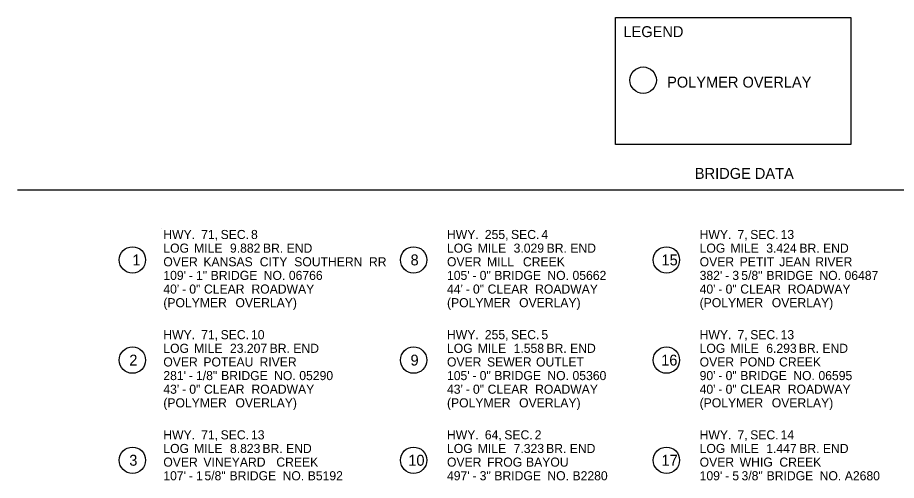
# Model space of a CAD drawing. Extents: x 1930546 to 1934225, y 596452 to 599553.
# Drawn here: x 1930546 to 1931513, y 599044 to 599553 of the extents above; entities that cross this region are included whole.
import ezdxf

# ---------------------------------------------------------------- set-up
doc = ezdxf.new("R2010")
doc.units = 0
doc.layers.add('Default', color=7, linetype='Continuous')
doc.layers.add('R_Border', color=7, linetype='Continuous')

msp = doc.modelspace()

# ---------------------------------------------------------------- linework, layer by layer
at = {"layer": 'R_Border'}
for p, q in [((1932141.6, 599363.54), (1930546.24, 599363.54)), ((1930704.61, 599321.69), (1930704.61, 599321.69))]:
    msp.add_line(p, q, dxfattribs=at)
msp.add_lwpolyline([(1931203.83, 599553.27), (1931462.74, 599553.27), (1931462.74, 599413.76), (1931203.83, 599413.76)], close=True, dxfattribs=at)
for centre in [(1931234.29, 599484.4), (1930672.53, 599286.71), (1930981.88, 599286.71), (1931259.86, 599286.71), (1930672.53, 599176.53), (1930981.88, 599176.53), (1931259.86, 599176.53), (1930672.53, 599066.36), (1930981.88, 599066.36), (1931259.86, 599066.36)]:
    msp.add_circle(centre, 14.52, dxfattribs=at)

# ---------------------------------------------------------------- texts
at = {"layer": 'Default'}
for s, p in [('HWY.', (1930706.56, 599309.69)), (' 71,', (1930744.47, 599309.69)), (' SEC.', (1930765.87, 599309.69)), (' 8', (1930799.28, 599309.69)), ('HWY.', (1931018.56, 599309.69)), (' 255,', (1931056.47, 599309.69)), (' SEC.', (1931085.26, 599309.69)), (' 4', (1931118.67, 599309.69)), ('HWY.', (1931296.43, 599309.69)), (' 7,', (1931334.34, 599309.69)), (' SEC.', (1931348.36, 599309.69)), (' 13', (1931381.77, 599309.69)), ('LOG', (1930706.56, 599294.69)), (' MILE', (1930736.69, 599294.69)), (' 9.882', (1930776.13, 599294.69)), (' BR.', (1930812.45, 599294.69)), (' END', (1930838.48, 599294.69)), ('LOG', (1931018.56, 599294.69)), (' MILE', (1931048.69, 599294.69)), (' 3.029', (1931088.13, 599294.69)), (' BR.', (1931124.43, 599294.69)), (' END', (1931150.46, 599294.69)), ('LOG', (1931296.43, 599294.69)), (' MILE', (1931326.56, 599294.69)), (' 3.424', (1931366, 599294.69)), (' BR.', (1931402.43, 599294.69)), (' END', (1931428.46, 599294.69)), ('OVER', (1930706.56, 599279.69)), (' KANSAS', (1930746.89, 599279.69)), (' CITY', (1930808.88, 599279.69)), (' SOUTHERN', (1930846.81, 599279.69)), (' RR', (1930929.03, 599279.69)), ('OVER', (1931018.56, 599279.69)), (' MILL', (1931058.89, 599279.69)), (' CREEK', (1931098.35, 599279.69)), ('OVER', (1931296.43, 599279.69)), (' PETIT', (1931336.76, 599279.69)), (' JEAN', (1931380.26, 599279.69)), (' RIVER', (1931419.83, 599279.69)), ("109'", (1930706.56, 599264.69)), (' 1"', (1930738.79, 599264.69)), (' BRIDGE', (1930754.92, 599264.69)), (' NO.', (1930813.24, 599264.69)), (' 06766', (1930840.9, 599264.69)), ("105'", (1931018.56, 599264.69)), (' 0"', (1931050.79, 599264.69)), (' BRIDGE', (1931066.92, 599264.69)), (' NO.', (1931125.24, 599264.69)), (' 05662', (1931152.9, 599264.69)), ("382'", (1931296.43, 599264.69)), (' 3', (1931328.66, 599264.69)), (' 5/8"', (1931338.51, 599264.69)), (' BRIDGE', (1931366.14, 599264.69)), (' NO.', (1931424.45, 599264.69)), (' 06487', (1931452.11, 599264.69)), (' -', (1930730.76, 599264.69)), (' -', (1931042.76, 599264.69)), (' -', (1931320.64, 599264.69)), ("40'", (1930706.56, 599249.69)), (' -', (1930723.37, 599249.69)), (' 0"', (1930731.4, 599249.69)), (' CLEAR', (1930747.53, 599249.69)), (' ROADWAY', (1930799.75, 599249.69)), ("44'", (1931018.56, 599249.69)), (' -', (1931035.37, 599249.69)), (' 0"', (1931043.4, 599249.69)), (' CLEAR', (1931059.53, 599249.69)), (' ROADWAY', (1931111.75, 599249.69)), ("40'", (1931296.43, 599249.69)), (' -', (1931313.25, 599249.69)), (' 0"', (1931321.28, 599249.69)), (' CLEAR', (1931337.41, 599249.69)), (' ROADWAY', (1931389.63, 599249.69)), ('(POLYMER', (1930706.56, 599234.69)), (' OVERLAY)', (1930782.17, 599234.69)), ('(POLYMER', (1931018.56, 599234.69)), (' OVERLAY)', (1931094.17, 599234.69)), ('(POLYMER', (1931296.43, 599234.69)), (' OVERLAY)', (1931372.04, 599234.69)), ('HWY.', (1930706.56, 599199.52)), (' 71,', (1930744.47, 599199.52)), (' SEC.', (1930765.87, 599199.52)), (' 10', (1930799.28, 599199.52)), ('HWY.', (1931018.56, 599199.52)), (' 255,', (1931056.47, 599199.52)), (' SEC.', (1931085.26, 599199.52)), (' 5', (1931118.67, 599199.52)), ('HWY.', (1931296.43, 599199.52)), (' 7,', (1931334.34, 599199.52)), (' SEC.', (1931348.36, 599199.52)), (' 13', (1931381.77, 599199.52)), ('LOG', (1930706.56, 599184.52)), (' MILE', (1930736.69, 599184.52)), (' 23.207', (1930776.13, 599184.52)), (' BR.', (1930819.79, 599184.52)), (' END', (1930845.82, 599184.52)), ('LOG', (1931018.56, 599184.52)), (' MILE', (1931048.69, 599184.52)), (' 1.558', (1931088.13, 599184.52)), (' BR.', (1931124.21, 599184.52)), (' END', (1931150.25, 599184.52)), ('LOG', (1931296.43, 599184.52)), (' MILE', (1931326.56, 599184.52)), (' 6.293', (1931366, 599184.52)), (' BR.', (1931401.71, 599184.52)), (' END', (1931427.74, 599184.52)), ('OVER', (1930706.56, 599169.52)), (' POTEAU', (1930746.89, 599169.52)), (' RIVER', (1930808.64, 599169.52)), ('OVER', (1931018.56, 599169.52)), (' SEWER', (1931058.89, 599169.52)), (' OUTLET', (1931112.75, 599169.52)), ('OVER', (1931296.43, 599169.52)), (' POND', (1931336.76, 599169.52)), (' CREEK', (1931380.09, 599169.52)), ("281'", (1930706.56, 599154.52)), (' 1/8"', (1930738.79, 599154.52)), (' BRIDGE', (1930766.42, 599154.52)), (' NO.', (1930824.73, 599154.52)), (' 05290', (1930852.39, 599154.52)), ("105'", (1931018.56, 599154.52)), (' 0"', (1931050.79, 599154.52)), (' BRIDGE', (1931066.92, 599154.52)), (' NO.', (1931125.24, 599154.52)), (' 05360', (1931152.9, 599154.52)), ("90'", (1931296.43, 599154.52)), (' 0"', (1931321.28, 599154.52)), (' BRIDGE', (1931337.41, 599154.52)), (' NO.', (1931395.72, 599154.52)), (' 06595', (1931423.38, 599154.52)), (' -', (1930730.76, 599154.52)), (' -', (1931042.76, 599154.52)), (' -', (1931313.25, 599154.52)), ("43'", (1930706.56, 599139.52)), (' 0"', (1930731.4, 599139.52)), (' CLEAR', (1930747.53, 599139.52)), (' ROADWAY', (1930799.75, 599139.52)), ("43'", (1931018.56, 599139.52)), (' 0"', (1931043.4, 599139.52)), (' CLEAR', (1931059.53, 599139.52)), (' ROADWAY', (1931111.75, 599139.52)), ("40'", (1931296.43, 599139.52)), (' 0"', (1931321.28, 599139.52)), (' CLEAR', (1931337.41, 599139.52)), (' ROADWAY', (1931389.63, 599139.52)), (' -', (1930723.37, 599139.52)), (' -', (1931035.37, 599139.52)), (' -', (1931313.25, 599139.52)), ('(POLYMER', (1930706.56, 599124.52)), (' OVERLAY)', (1930782.17, 599124.52)), ('(POLYMER', (1931018.56, 599124.52)), (' OVERLAY)', (1931094.17, 599124.52)), ('(POLYMER', (1931296.43, 599124.52)), (' OVERLAY)', (1931372.04, 599124.52)), ('HWY.', (1930706.56, 599089.34)), (' 71,', (1930744.47, 599089.34)), (' SEC.', (1930765.87, 599089.34)), (' 13', (1930799.28, 599089.34)), ('HWY.', (1931018.56, 599089.34)), (' 64,', (1931056.47, 599089.34)), (' SEC.', (1931077.87, 599089.34)), (' 2', (1931111.28, 599089.34)), ('HWY.', (1931296.43, 599089.34)), (' 7,', (1931334.34, 599089.34)), (' SEC.', (1931348.36, 599089.34)), (' 14', (1931381.77, 599089.34)), ('LOG', (1930706.56, 599074.34)), (' MILE', (1930736.69, 599074.34)), (' 8.823', (1930776.13, 599074.34)), (' BR.', (1930811.83, 599074.34)), (' END', (1930837.86, 599074.34)), ('LOG', (1931018.56, 599074.34)), (' MILE', (1931048.69, 599074.34)), (' 7.323', (1931088.13, 599074.34)), (' BR.', (1931123.83, 599074.34)), (' END', (1931149.86, 599074.34)), ('LOG', (1931296.43, 599074.34)), (' MILE', (1931326.56, 599074.34)), (' 1.447', (1931366, 599074.34)), (' BR.', (1931402.27, 599074.34)), (' END', (1931428.3, 599074.34)), ('OVER', (1930706.56, 599059.34)), (' VINEYARD', (1930746.89, 599059.34)), (' CREEK', (1930827.12, 599059.34)), ('OVER', (1931018.56, 599059.34)), (' FROG', (1931058.89, 599059.34)), (' BAYOU', (1931101.75, 599059.34)), ('OVER', (1931296.43, 599059.34)), (' WHIG', (1931336.76, 599059.34)), (' CREEK', (1931380.42, 599059.34)), ("107'", (1930706.56, 599044.34)), (' -', (1930730.76, 599044.34)), (' 1', (1930738.79, 599044.34)), (' 5/8"', (1930748.05, 599044.34)), (' BRIDGE', (1930775.68, 599044.34)), (' NO.', (1930834, 599044.34)), (' B5192', (1930861.66, 599044.34)), ("497'", (1931018.56, 599044.34)), (' -', (1931042.76, 599044.34)), (' 3"', (1931050.79, 599044.34)), (' BRIDGE', (1931066.92, 599044.34)), (' NO.', (1931125.24, 599044.34)), (' B2280', (1931152.9, 599044.34)), ("109'", (1931296.43, 599044.34)), (' -', (1931320.64, 599044.34)), (' 5', (1931328.66, 599044.34)), (' 3/8"', (1931338.77, 599044.34)), (' BRIDGE', (1931366.4, 599044.34)), (' NO.', (1931424.71, 599044.34)), (' A2680', (1931452.37, 599044.34))]:
    msp.add_text(s, height=10, dxfattribs=at).set_placement(p)
at = {"layer": 'R_Border'}
for s, p in [('LEGEND', (1931212.64, 599531.8)), ('POLYMER OVERLAY', (1931260.65, 599476.28)), ('BRIDGE DATA', (1931291.18, 599375.86)), ('1', (1930672.53, 599280.71)), ('8', (1930978.48, 599280.71)), ('15', (1931254.48, 599280.71)), ('2', (1930669.12, 599170.53)), ('9', (1930978.43, 599170.53)), ('16', (1931254.15, 599170.53)), ('3', (1930669.12, 599060.36)), ('10', (1930975.98, 599060.36)), ('17', (1931254.48, 599060.36))]:
    msp.add_text(s, height=12, rotation=360, dxfattribs=at).set_placement(p)

doc.saveas('drawing.dxf')
